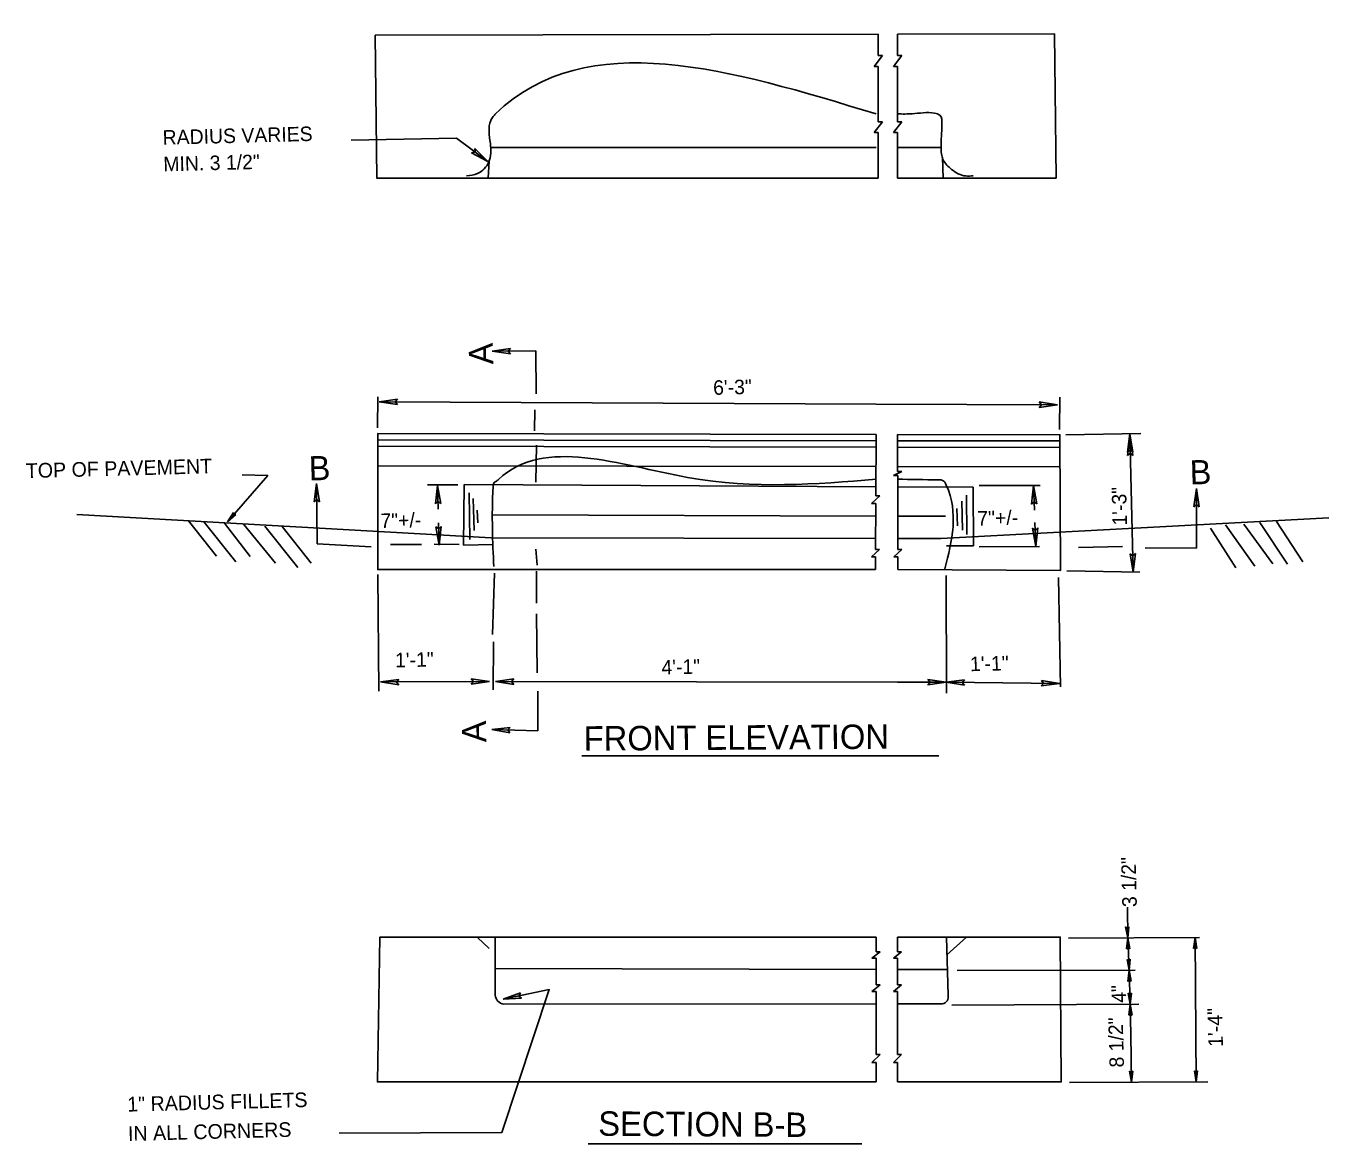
# Model space of a CAD drawing. Extents: x 1.75 to 8.12, y 0.37 to 10.28.
# Drawn here: x 1.75 to 7.08, y 5.71 to 10.28 of the extents above; entities that cross this region are included whole.
import ezdxf

# ---------------------------------------------------------------- set-up
doc = ezdxf.new("R2010")
doc.units = 0
for name, color, linetype in [('DETL-DIMS', 7, 'Continuous'), ('DETL-LINE', 7, 'Continuous'), ('DETL-NOTE', 7, 'Continuous'), ('DETL-TITL', 7, 'Continuous')]:
    doc.layers.add(name, color=color, linetype=linetype)

msp = doc.modelspace()

# ---------------------------------------------------------------- linework, layer by layer
at = {"layer": 'DETL-DIMS'}
for p, q in [((3.5708, 9.764), (3.5849, 9.7672)), ((3.5708, 9.764), (3.6377, 9.7283)), ((3.5838, 9.7816), (3.6377, 9.7283)), ((3.5838, 9.7816), (3.5849, 9.7672)), ((3.7297, 8.964), (3.6547, 8.9526)), ((3.8334, 8.9537), (3.6548, 8.9526)), ((3.7297, 8.964), (3.7204, 8.953)), ((3.7298, 8.9421), (3.7204, 8.953)), ((3.8344, 8.7784), (3.8334, 8.9537)), ((3.7298, 8.9421), (3.6547, 8.9526)), ((3.1859, 8.6392), (3.1877, 8.7656)), ((3.2683, 8.7561), (3.1933, 8.7455)), ((3.2683, 8.7561), (3.1933, 8.7455)), ((3.2683, 8.7342), (3.1933, 8.7455)), ((3.2683, 8.7342), (3.1933, 8.7455)), ((3.1933, 8.7455), (5.2255, 8.7364)), ((3.2683, 8.7561), (3.2589, 8.7452)), ((3.2683, 8.7561), (3.2589, 8.7452)), ((3.2683, 8.7342), (3.2589, 8.7452)), ((3.2683, 8.7342), (3.2589, 8.7452)), ((5.8931, 8.7448), (5.968, 8.7335)), ((5.8931, 8.7448), (5.9024, 8.7338)), ((5.9756, 8.6326), (5.9773, 8.7641)), ((3.828, 8.627), (3.8293, 8.713)), ((5.2255, 8.7364), (5.968, 8.7335)), ((5.893, 8.7229), (5.9024, 8.7338)), ((5.893, 8.7229), (5.968, 8.7335)), ((6.3077, 8.6154), (6.002, 8.611)), ((6.2538, 8.5395), (6.2628, 8.6148)), ((6.2757, 8.54), (6.2628, 8.6148)), ((6.2773, 8.0493), (6.2629, 8.6148)), ((3.8334, 8.4174), (3.8364, 8.5688)), ((6.2538, 8.5395), (6.2645, 8.5492)), ((6.2757, 8.54), (6.2645, 8.5492)), ((2.9267, 8.3365), (2.9368, 8.4116)), ((2.9368, 8.4116), (2.9397, 8.1642)), ((2.9486, 8.3368), (2.9368, 8.4116)), ((3.5141, 8.4058), (3.3904, 8.4061)), ((3.4227, 8.3285), (3.4317, 8.4037)), ((3.4446, 8.329), (3.4317, 8.4037)), ((3.4342, 8.3068), (3.4317, 8.4037)), ((5.6465, 8.4034), (5.8968, 8.4026)), ((5.8613, 8.3273), (5.8694, 8.4027)), ((5.8832, 8.3281), (5.8694, 8.4027)), ((5.8694, 8.4027), (5.8733, 8.3023)), ((6.5254, 8.3167), (6.5366, 8.3916)), ((6.536, 8.1475), (6.5366, 8.3916)), ((6.5473, 8.3166), (6.5366, 8.3916)), ((2.9267, 8.3365), (2.9375, 8.346)), ((2.9486, 8.3368), (2.9375, 8.346)), ((3.4227, 8.3285), (3.4334, 8.3381)), ((3.4446, 8.329), (3.4334, 8.3381)), ((5.8613, 8.3273), (5.8719, 8.3371)), ((5.8832, 8.3281), (5.8719, 8.3371)), ((6.5254, 8.3167), (6.5364, 8.326)), ((6.5473, 8.3166), (6.5364, 8.326)), ((2.5969, 8.2931), (2.5722, 8.2548)), ((2.6067, 8.2844), (2.5722, 8.2548)), ((2.5969, 8.2931), (2.5981, 8.2845)), ((2.6067, 8.2844), (2.5981, 8.2845)), ((3.4251, 8.2345), (3.438, 8.1598)), ((3.4251, 8.2345), (3.4363, 8.2254)), ((3.438, 8.1598), (3.4357, 8.2505)), ((3.447, 8.2351), (3.4363, 8.2254)), ((3.447, 8.2351), (3.438, 8.1598)), ((5.8651, 8.2287), (5.879, 8.1541)), ((5.8651, 8.2287), (5.8764, 8.2197)), ((5.8752, 8.2518), (5.879, 8.1541)), ((5.887, 8.2295), (5.8764, 8.2197)), ((5.887, 8.2295), (5.879, 8.1541)), ((2.9397, 8.1642), (3.1599, 8.1527)), ((3.2387, 8.1616), (3.3658, 8.1614)), ((3.4173, 8.1627), (3.5204, 8.1619)), ((5.6473, 8.1522), (5.8935, 8.1537)), ((6.2332, 8.1545), (6.0539, 8.1499)), ((3.8387, 8.0772), (3.8336, 8.1424)), ((6.2645, 8.1241), (6.2773, 8.0493)), ((6.2645, 8.1241), (6.2757, 8.115)), ((6.2864, 8.1246), (6.2757, 8.115)), ((6.2864, 8.1246), (6.2773, 8.0493)), ((6.3263, 8.149), (6.536, 8.1475)), ((3.8358, 7.9225), (3.8359, 8.0531)), ((6.0058, 8.0549), (6.3048, 8.0488)), ((3.1868, 8.0399), (3.1922, 7.5622)), ((3.6569, 7.7941), (3.6643, 8.0453)), ((5.5135, 7.5541), (5.5115, 8.0353)), ((5.9721, 8.0265), (5.9801, 7.5798)), ((3.8396, 7.6372), (3.8369, 7.8778)), ((3.6593, 7.5673), (3.6612, 7.7633)), ((3.2732, 7.6102), (3.198, 7.6002)), ((3.2729, 7.5884), (3.198, 7.6002)), ((3.1981, 7.6002), (3.6447, 7.6013)), ((3.2732, 7.6102), (3.2637, 7.5994)), ((3.2729, 7.5884), (3.2637, 7.5994)), ((3.5696, 7.5912), (3.5791, 7.6021)), ((3.5696, 7.5912), (3.6447, 7.6013)), ((3.5698, 7.6131), (3.6447, 7.6013)), ((3.5698, 7.6131), (3.5791, 7.6021)), ((3.7438, 7.612), (3.6687, 7.6019)), ((3.6687, 7.6019), (5.3133, 7.5991)), ((3.7436, 7.5901), (3.6687, 7.6019)), ((3.7438, 7.612), (3.7343, 7.6012)), ((3.7436, 7.5901), (3.7343, 7.6012)), ((5.3133, 7.5991), (5.5124, 7.5988)), ((5.4372, 7.5887), (5.4467, 7.5995)), ((5.4372, 7.5887), (5.5123, 7.5988)), ((5.4375, 7.6106), (5.5123, 7.5988)), ((5.4375, 7.6106), (5.4467, 7.5995)), ((5.5875, 7.6088), (5.5123, 7.5988)), ((5.5872, 7.587), (5.5123, 7.5988)), ((5.5124, 7.5988), (5.9763, 7.5935)), ((5.5875, 7.6088), (5.578, 7.598)), ((5.5872, 7.587), (5.578, 7.598)), ((5.9012, 7.5834), (5.9107, 7.5942)), ((5.9012, 7.5834), (5.9763, 7.5935)), ((5.9015, 7.6053), (5.9763, 7.5935)), ((5.9015, 7.6053), (5.9107, 7.5942)), ((3.8423, 7.4001), (3.8416, 7.5616)), ((3.7284, 7.4143), (3.6532, 7.4056)), ((3.7284, 7.4143), (3.7188, 7.4037)), ((3.6532, 7.4056), (3.8423, 7.4001)), ((3.7278, 7.3925), (3.6532, 7.4056)), ((3.7278, 7.3925), (3.7188, 7.4037)), ((6.2546, 6.5537), (6.2541, 6.6793)), ((6.0126, 6.5524), (6.5484, 6.5552)), ((6.2461, 6.5984), (6.2546, 6.5537)), ((6.2461, 6.5984), (6.2529, 6.593)), ((6.2592, 6.5989), (6.2529, 6.593)), ((6.2592, 6.5989), (6.2546, 6.5537)), ((6.5239, 6.5101), (6.5302, 6.5552)), ((6.5371, 6.5102), (6.5302, 6.5552)), ((6.5342, 5.9649), (6.5302, 6.5551)), ((6.2501, 6.5084), (6.2546, 6.5537)), ((6.2501, 6.5084), (6.2563, 6.5144)), ((6.2605, 6.4208), (6.2546, 6.5537)), ((6.2632, 6.509), (6.2546, 6.5537)), ((6.2632, 6.509), (6.2563, 6.5144)), ((6.5239, 6.5101), (6.5304, 6.5157)), ((6.5371, 6.5102), (6.5304, 6.5157)), ((6.2519, 6.4655), (6.2605, 6.4208)), ((6.2519, 6.4655), (6.2588, 6.4602)), ((6.2651, 6.4661), (6.2588, 6.4602)), ((6.2651, 6.4661), (6.2605, 6.4208)), ((5.5566, 6.4204), (6.2857, 6.4208)), ((6.2553, 6.3756), (6.2603, 6.4208)), ((6.2652, 6.2824), (6.2603, 6.4208)), ((6.2685, 6.3761), (6.2603, 6.4208)), ((6.2553, 6.3756), (6.2617, 6.3815)), ((6.2685, 6.3761), (6.2617, 6.3815)), ((3.7713, 6.3282), (3.7001, 6.3021)), ((3.7757, 6.3068), (3.7001, 6.3021)), ((3.7713, 6.3282), (3.7643, 6.3156)), ((3.7757, 6.3068), (3.7643, 6.3156)), ((6.257, 6.3271), (6.2652, 6.2824)), ((6.257, 6.3271), (6.2638, 6.3217)), ((6.2701, 6.3276), (6.2638, 6.3217)), ((6.2701, 6.3276), (6.2652, 6.2824)), ((5.5348, 6.2776), (6.3002, 6.2826)), ((6.2592, 6.2373), (6.2651, 6.2824)), ((6.2592, 6.2373), (6.2657, 6.243)), ((6.2723, 6.2375), (6.2651, 6.2824)), ((6.267, 6.1576), (6.2651, 6.2824)), ((6.2723, 6.2375), (6.2657, 6.243)), ((6.2698, 5.9632), (6.267, 6.1576)), ((6.2626, 6.0082), (6.2698, 5.9633)), ((6.2626, 6.0082), (6.2692, 6.0026)), ((6.2757, 6.0083), (6.2692, 6.0026)), ((6.2757, 6.0083), (6.2698, 5.9633)), ((6.5273, 6.0098), (6.5342, 5.9649)), ((6.5273, 6.0098), (6.5339, 6.0043)), ((6.5404, 6.0099), (6.5339, 6.0043)), ((6.5404, 6.0099), (6.5342, 5.9649)), ((6.0168, 5.9617), (6.5818, 5.9652))]:
    msp.add_line(p, q, dxfattribs=at)
for points in [[(3.6377, 9.7283), (3.509, 9.8232), (3.0778, 9.8157)], [(2.5722, 8.2548), (2.7373, 8.444), (2.6323, 8.4463)], [(3.0297, 5.755), (3.6941, 5.7571), (3.8889, 6.3419), (3.7001, 6.3021)]]:
    msp.add_lwpolyline(points, dxfattribs=at)
at = {"layer": 'DETL-LINE'}
for p, q in [((5.2344, 10.249), (5.2344, 10.1615)), ((5.3136, 10.249), (5.3136, 10.1615)), ((5.2176, 10.1168), (5.2511, 10.1615)), ((5.2344, 10.1615), (5.2511, 10.1615)), ((5.2968, 10.1168), (5.3303, 10.1615)), ((5.3136, 10.1615), (5.3303, 10.1615)), ((5.2176, 10.1168), (5.2344, 10.1168)), ((5.2344, 10.1168), (5.2344, 9.8903)), ((5.2968, 10.1168), (5.3136, 10.1168)), ((5.3136, 10.1168), (5.3136, 9.8903)), ((5.2176, 9.8469), (5.2511, 9.8903)), ((5.2344, 9.8903), (5.2511, 9.8903)), ((5.2968, 9.8469), (5.3303, 9.8903)), ((5.3136, 9.8903), (5.3303, 9.8903)), ((5.2176, 9.8469), (5.2344, 9.8469)), ((5.2344, 9.8469), (5.2344, 9.6606)), ((5.2968, 9.8469), (5.3136, 9.8469)), ((5.3136, 9.8469), (5.3136, 9.6606)), ((3.652, 9.7855), (5.2255, 9.7853)), ((5.3133, 9.7853), (5.491, 9.7853)), ((3.6422, 9.7294), (3.6392, 9.6606)), ((5.4964, 9.7456), (5.5003, 9.6606)), ((3.1868, 8.59), (5.2255, 8.5865)), ((5.2255, 8.6118), (5.2243, 8.3604)), ((5.3136, 8.4605), (5.3133, 8.6118)), ((5.3133, 8.5865), (5.9773, 8.5853)), ((3.1867, 8.5635), (5.2255, 8.56)), ((5.3133, 8.56), (5.9773, 8.5588)), ((3.1866, 8.484), (5.2255, 8.4804)), ((5.3133, 8.4804), (5.9771, 8.4793)), ((5.2969, 8.4441), (5.3304, 8.4605)), ((5.2969, 8.4441), (5.3137, 8.4441)), ((5.3136, 8.4605), (5.3304, 8.4605)), ((5.3144, 8.1421), (5.3137, 8.4441)), ((3.5379, 8.1587), (3.54, 8.4075)), ((3.54, 8.4075), (5.2255, 8.3981)), ((3.5608, 8.3734), (3.564, 8.1826)), ((5.3133, 8.3981), (5.6227, 8.3964)), ((5.6227, 8.3964), (5.6232, 8.1561)), ((3.5776, 8.3499), (3.581, 8.2193)), ((5.2073, 8.329), (5.241, 8.3604)), ((5.2073, 8.329), (5.2241, 8.329)), ((5.2241, 8.329), (5.2232, 8.1421)), ((5.2243, 8.3604), (5.241, 8.3604)), ((5.5763, 8.3398), (5.5794, 8.2209)), ((5.5958, 8.3638), (5.5971, 8.2024)), ((3.594, 8.3026), (3.5959, 8.2501)), ((3.6562, 8.2832), (5.2255, 8.2782)), ((5.3133, 8.2782), (5.5099, 8.2776)), ((5.5559, 8.3097), (5.5583, 8.2383)), ((2.4134, 8.259), (2.5275, 8.1137)), ((2.4771, 8.2531), (2.6067, 8.0915)), ((2.5604, 8.2492), (2.6652, 8.1127)), ((2.6391, 8.2436), (2.7687, 8.0851)), ((2.7255, 8.2368), (2.8598, 8.0678)), ((2.7966, 8.2356), (2.9153, 8.0858)), ((6.5931, 8.2282), (6.697, 8.066)), ((6.6546, 8.2424), (6.7741, 8.0739)), ((6.7301, 8.2456), (6.8481, 8.0835)), ((6.7952, 8.2524), (6.9083, 8.0812)), ((6.8629, 8.2555), (6.9708, 8.0918)), ((3.6593, 8.1618), (3.5379, 8.1587)), ((5.6232, 8.1561), (5.513, 8.1561)), ((5.2063, 8.1122), (5.2399, 8.1421)), ((5.2063, 8.1122), (5.223, 8.1122)), ((5.223, 8.1122), (5.2228, 8.0596)), ((5.2232, 8.1421), (5.2399, 8.1421)), ((5.2975, 8.1122), (5.3312, 8.1421)), ((5.2975, 8.1122), (5.3143, 8.1122)), ((5.3144, 8.1421), (5.3312, 8.1421)), ((5.3146, 8.0596), (5.3145, 8.1122)), ((5.2255, 6.5565), (5.2255, 6.4967)), ((5.3133, 6.4967), (5.3133, 6.5565)), ((5.5196, 6.319), (5.5135, 6.5559)), ((5.5153, 6.4844), (5.5957, 6.5565)), ((3.5957, 6.5547), (3.6424, 6.5103)), ((3.6668, 6.5547), (3.6673, 6.3194)), ((5.2087, 6.471), (5.2422, 6.4967)), ((5.2087, 6.471), (5.2255, 6.471)), ((5.2255, 6.4967), (5.2422, 6.4967)), ((5.2255, 6.471), (5.2255, 6.3613)), ((5.2965, 6.471), (5.33, 6.4967)), ((5.2965, 6.471), (5.3133, 6.471)), ((5.3133, 6.4967), (5.33, 6.4967)), ((5.3133, 6.3613), (5.3133, 6.471)), ((3.6671, 6.428), (5.2255, 6.4243)), ((5.3133, 6.4243), (5.5169, 6.4238)), ((5.2087, 6.3342), (5.2422, 6.3613)), ((5.2255, 6.3613), (5.2422, 6.3613)), ((5.2965, 6.3342), (5.33, 6.3613)), ((5.3133, 6.3613), (5.33, 6.3613)), ((5.2087, 6.3342), (5.2255, 6.3342)), ((5.2255, 6.3342), (5.2255, 6.0761)), ((5.2965, 6.3342), (5.3133, 6.3342)), ((5.3133, 6.0761), (5.3133, 6.3342)), ((3.7029, 6.282), (5.2255, 6.2836)), ((5.3133, 6.2836), (5.4968, 6.2838)), ((5.2087, 6.0433), (5.2423, 6.0761)), ((5.2255, 6.0761), (5.2423, 6.0761)), ((5.2965, 6.0433), (5.33, 6.0761)), ((5.3133, 6.0761), (5.33, 6.0761)), ((5.2087, 6.0433), (5.2255, 6.0433)), ((5.2255, 6.0433), (5.2255, 5.9646)), ((5.2965, 6.0433), (5.3133, 6.0433)), ((5.3133, 5.9646), (5.3133, 6.0433))]:
    msp.add_line(p, q, dxfattribs=at)
for points in [[(5.2344, 9.6606), (3.1832, 9.6606), (3.1771, 10.2442), (5.2344, 10.249)], [(5.3136, 10.249), (5.9546, 10.2505), (5.9618, 9.6605), (5.3136, 9.6606)], [(5.2255, 8.6118), (3.1868, 8.6153), (3.1868, 8.0596), (5.2228, 8.0596)], [(5.3146, 8.0596), (5.9802, 8.0563), (5.9774, 8.6107), (5.3133, 8.6118)], [(1.9568, 8.2852), (3.6504, 8.1897), (5.2255, 8.1872)], [(5.3133, 8.1872), (5.4901, 8.1869), (7.0777, 8.271)], [(5.2255, 5.9646), (3.1855, 5.9646), (3.1959, 6.5568), (5.2255, 6.5565)], [(5.3133, 6.5565), (5.9788, 6.5564), (5.983, 5.9646), (5.3133, 5.9646)]]:
    msp.add_lwpolyline(points, dxfattribs=at)
for centre, radius, start, end in [((3.7084, 6.3229), 0.0412, 184.8042, 262.3778), ((5.4924, 6.3116), 0.0282, 279.0422, 15.1587)]:
    msp.add_arc(centre, radius, start, end, dxfattribs=at)
for points in [[(3.5507, 9.67), (3.5955, 9.6793), (3.6414, 9.7256), (3.6477, 9.8016), (3.6493, 9.8959), (3.6592, 9.9125), (3.6691, 9.923), (5.2255, 9.9227)], [(5.3133, 9.9227), (5.3728, 9.9234), (5.4649, 9.9258), (5.4856, 9.9181), (5.4948, 9.8794), (5.491, 9.7871), (5.5003, 9.7343), (5.5341, 9.6962), (5.5921, 9.669), (5.6228, 9.6698)], [(3.6616, 8.0714), (3.6589, 8.3992), (3.6641, 8.4163), (3.6697, 8.4193), (3.6807, 8.428), (4.4547, 8.4366), (5.2255, 8.429)], [(5.3133, 8.429), (5.4807, 8.4267), (5.4977, 8.4243), (5.5123, 8.4049), (5.507, 8.0627)]]:
    msp.add_spline(points, degree=3, dxfattribs=at)
at = {"layer": 'DETL-TITL'}
for p, q in [((6.2542, 8.5259), (6.2632, 8.6012)), ((6.2761, 8.5265), (6.2632, 8.6012)), ((6.2542, 8.5259), (6.2649, 8.5356)), ((6.2761, 8.5265), (6.2649, 8.5356)), ((4.0224, 7.298), (5.4827, 7.298)), ((4.0471, 5.7107), (5.1675, 5.7107))]:
    msp.add_line(p, q, dxfattribs=at)

# ---------------------------------------------------------------- texts
at = {"layer": 'DETL-NOTE'}
for s, height, rotation, p in [('RADIUS VARIES', 0.059406, 1.4676, (2.3079, 9.7966)), ('MIN. 3 1/2"', 0.059406, 1.4676, (2.3107, 9.6878)), ('6\'-3"', 0.05941, 1.4676, (4.5596, 8.7737)), ('TOP OF PAVEMENT', 0.06, 1.4676, (1.7483, 8.4336)), ('1\'-3"', 0.05941, 91.4676, (6.2522, 8.2403)), ('7"+/-', 0.05941, 1.4676, (3.1987, 8.229)), ('7"+/-', 0.05941, 1.4676, (5.64, 8.2389)), ('1\'-1"', 0.05941, 1.4676, (3.2587, 7.6592)), ('4\'-1"', 0.05941, 1.4676, (4.3483, 7.63)), ('1\'-1"', 0.05941, 1.4676, (5.6101, 7.6437)), ('3 1/2"', 0.05941, 91.4676, (6.2921, 6.68)), ('4"', 0.05941, 91.4676, (6.2488, 6.2887)), ('1\'-4"', 0.06, 91.4676, (6.6444, 6.1082)), ('8 1/2"', 0.05941, 91.4676, (6.2396, 6.024)), ('1" RADIUS FILLETS ', 0.06, 1.4676, (2.1632, 5.8428)), ('IN ALL CORNERS', 0.06, 1.4676, (2.1662, 5.7228))]:
    msp.add_text(s, height=height, rotation=rotation, dxfattribs=at).set_placement(p)
at = {"layer": 'DETL-TITL'}
for s, height, rotation, p in [('A', 0.099, 91.4676, (3.6598, 8.8993)), ('B', 0.099, 1.4676, (2.9062, 8.4238)), ('B', 0.099, 1.4676, (6.5095, 8.4073)), ('A', 0.099, 91.4676, (3.6315, 7.3535)), ('FRONT ELEVATION', 0.1, 0.3568, (4.03, 7.3188)), ('SECTION B-B', 0.1, 359.6451, (4.0888, 5.7442))]:
    msp.add_text(s, height=height, rotation=rotation, dxfattribs=at).set_placement(p)

doc.saveas('drawing.dxf')
